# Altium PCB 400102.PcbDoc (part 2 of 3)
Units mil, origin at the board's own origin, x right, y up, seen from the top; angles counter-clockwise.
Board outline 3703.69 x 2381.89 mil, 2 copper layers (Top Layer, Bottom Layer), stack 61.8 mil thick; 220 components, 149 nets, 880 pads, 750 vias.
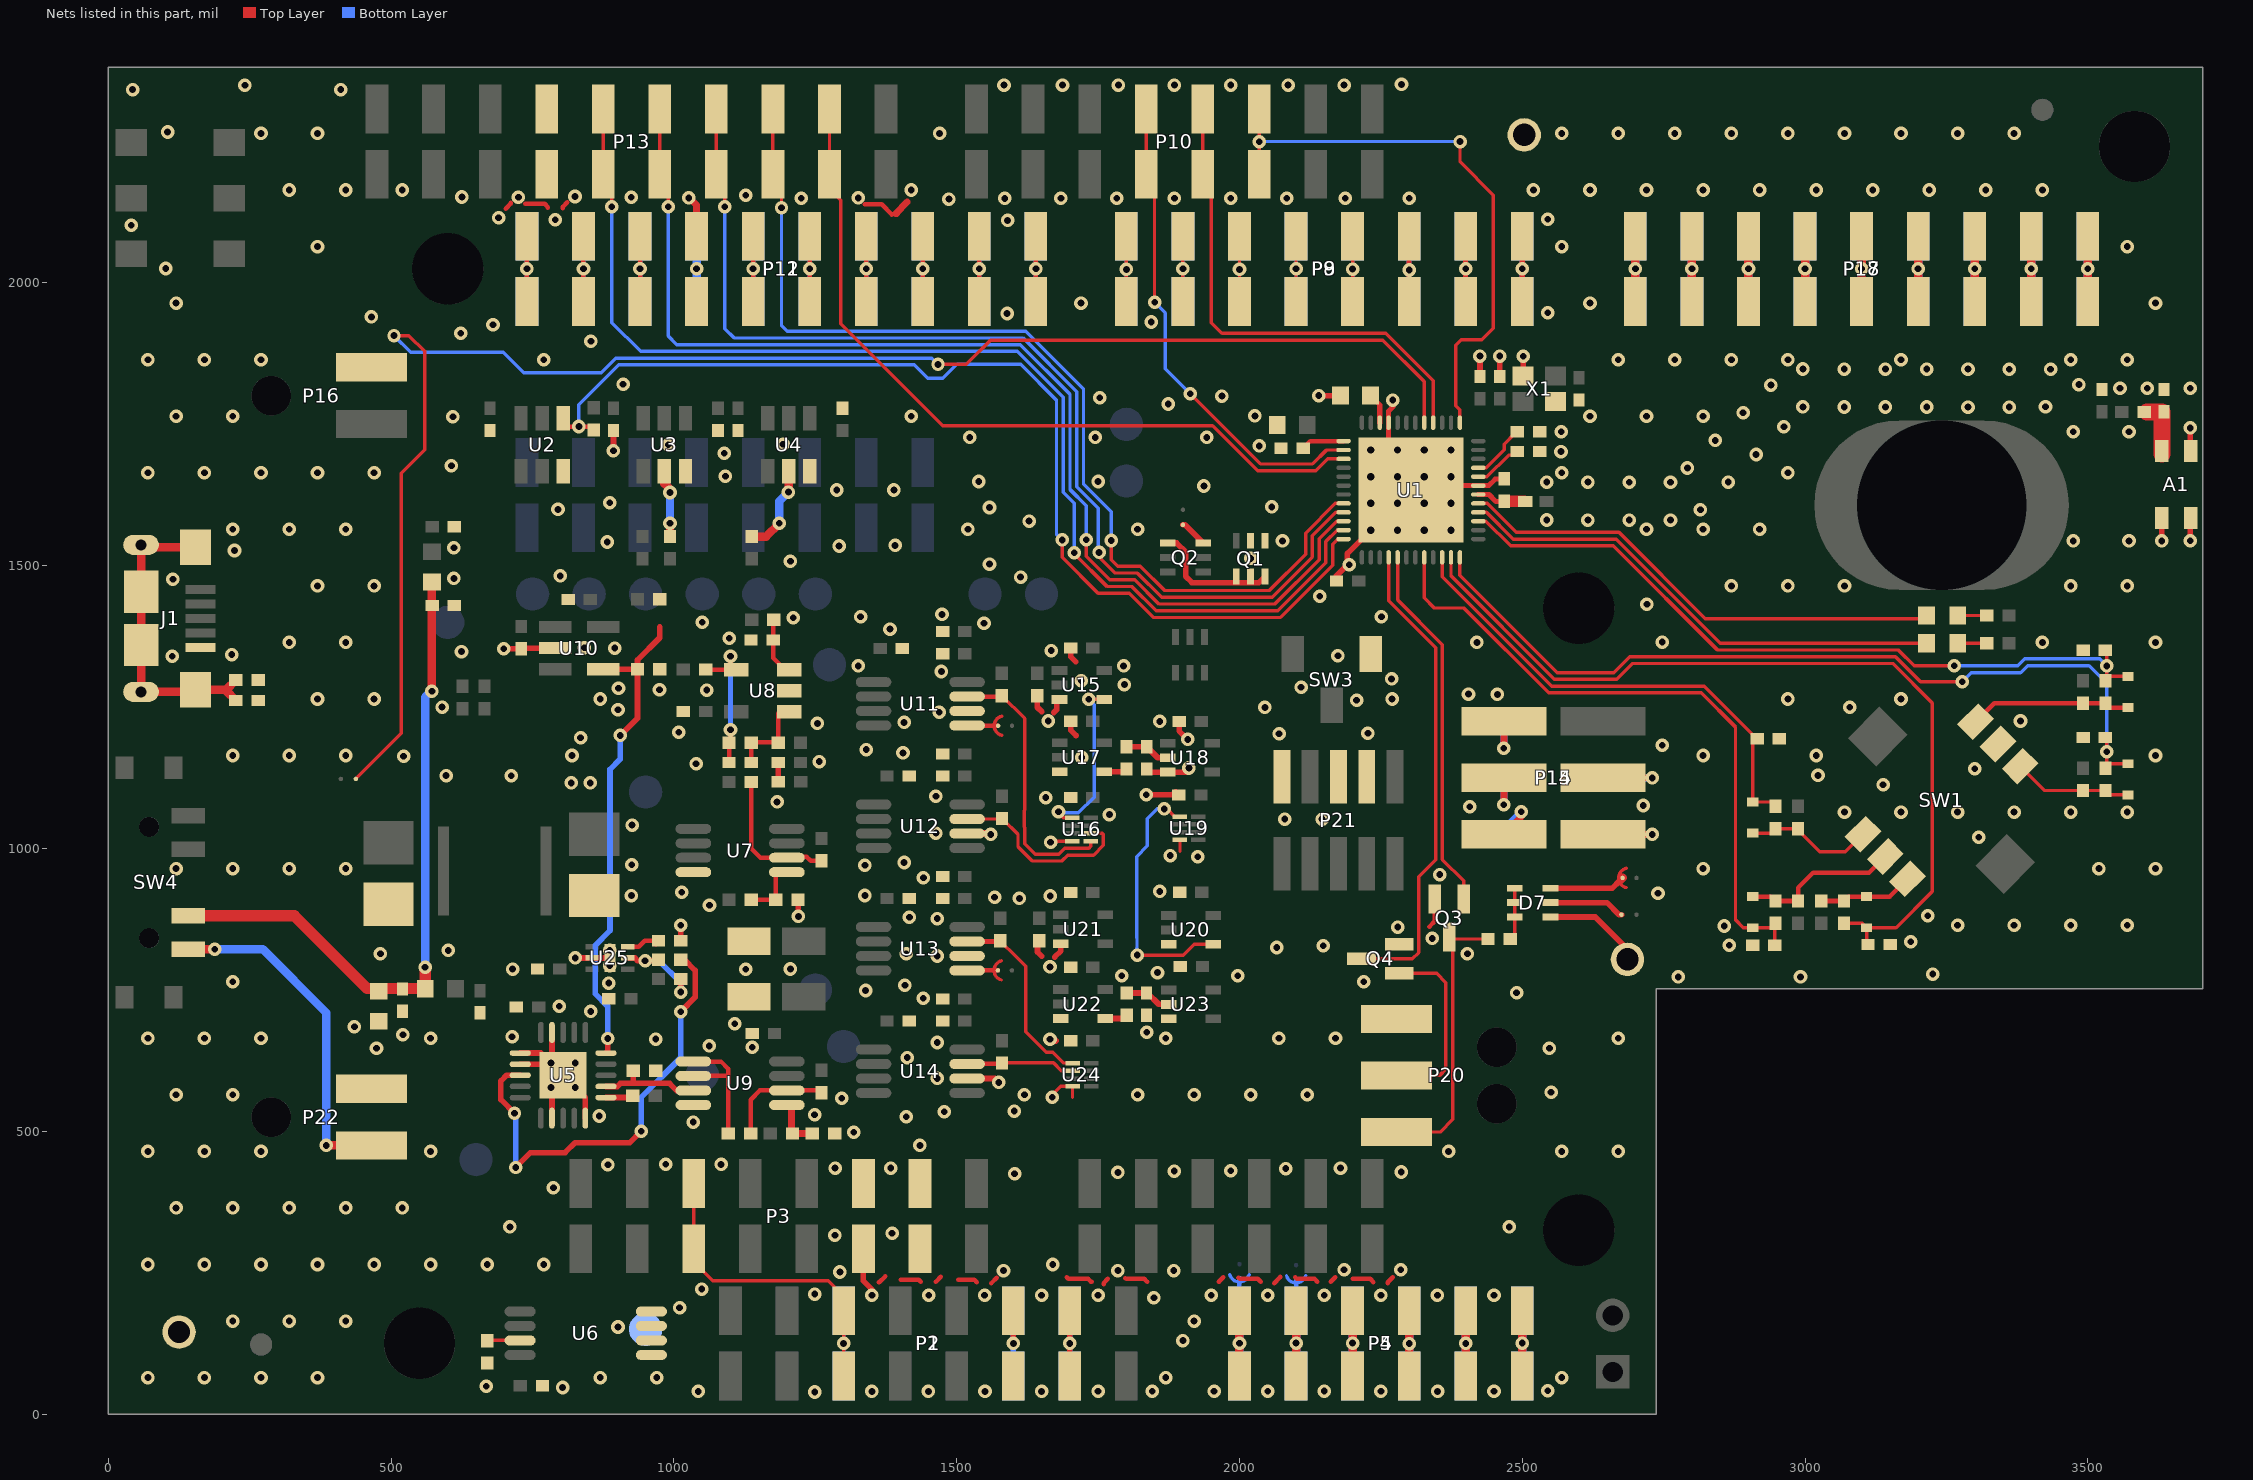
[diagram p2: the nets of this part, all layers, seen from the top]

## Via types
v1: diameter 24, hole 12, Top Layer to Bottom Layer, tented both sides, 666 vias
v2: diameter 23.62, hole 11.81, Top Layer to Bottom Layer, tented both sides, 68 vias
v3: diameter 25.98, hole 12.99, Top Layer to Bottom Layer, tented both sides, 16 vias

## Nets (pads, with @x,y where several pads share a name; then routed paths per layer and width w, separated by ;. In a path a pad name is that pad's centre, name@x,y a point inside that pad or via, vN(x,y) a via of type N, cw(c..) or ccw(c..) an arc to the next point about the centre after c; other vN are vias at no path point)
D2: P10.3 U1.37 | length 1044.3
  Top Layer w6: P10.3@2035,2192.17 v1(2035,2249.84) P10.3@2035,2307.52 ; U1.37@2389.76,1752.95 2389.76,1775.65 2382.22,1783.2 2382.22,1889.76 2391.89,1899.43 2428.43,1899.43 2449,1920 2449,2155 2390,2214 v1(2390,2250)
  Bottom Layer w6: v1(2035,2249.84) 2035.39,2250.23 2389.77,2250.23 v1(2390,2250)
D3: P10.4 U1.40 | length 892.9
  Top Layer w6: P10.4@1935,2307.52 P10.4@1935,2192.17 1935,2165.53 1950,2150.53 1950,1930 1969,1911 2258.41,1911 2342.52,1826.89 U1.40@2342.52,1752.95
D4: P10.5 U1.2 | length 868.3
  Top Layer w6: P10.5@1835,2307.52 P10.5@1835,2192.17 1849.69,2177.48 v2@1849.69,1966 ; v2(1913.11,1804) 2037.11,1680 2129.15,1680 2153.87,1704.72 U1.2@2184.06,1704.72
  Bottom Layer w6: v2(1850,1966) 1869,1947 1869,1848.11 v2(1913.11,1804)
D9: P13.2 U1.3 | length 1393.2
  Top Layer w6: P13.2@1275,2307.52 P13.2@1275,2192.17 1275,2166 1295,2146 1295,1927.91 1475,1747.91 1952.37,1747.91 2032.18,1668.09 2135.04,1668.09 2155.92,1688.98 U1.3@2184.06,1688.98
D10: P13.3 U1.8 | length 1789.3
  Top Layer w6: P13.3@1175,2192.17 P13.3@1175,2307.52 ; v2(1190.13,2133) P13.3@1190.13,2177.04 ; v1(1773.15,1544.64) 1773.15,1510.85 1784.94,1499.05 1824.63,1499.05 1867.47,1456.21 2052.86,1456.21 2117,1520.35 2117,1557.72 2169.52,1610.24 U1.8@2184.06,1610.24
  Bottom Layer w6: v2(1190.13,2133) 1190.13,1925 1200.41,1914.72 1622.12,1914.72 1724.09,1812.74 1724.09,1644.74 1773.15,1595.69 v1(1773.15,1544.64)
D11: P13.4 U1.9 | length 1917.6
  Top Layer w6: P13.4@1075,2307.52 P13.4@1075,2192.17 1090,2177.16 v1(1090,2135) ; v1(1751.82,1523.61) 1751.82,1515.34 1780.01,1487.15 1819.7,1487.15 1862.54,1444.31 2057.8,1444.31 2128.91,1515.42 2128.91,1552.79 2170.6,1594.49 U1.9@2184.06,1594.49
  Bottom Layer w6: v1(1090,2135) 1090,1919 1106.19,1902.81 1617.19,1902.81 1712.19,1807.81 1712.19,1639.81 1750.05,1601.95 1750.05,1525.39 v1(1751.82,1523.61)
D12: P13.5 U1.10 | length 2031.2
  Top Layer w6: P13.5@975,2307.52 P13.5@975,2192.17 989.76,2177.4 v1(989.76,2135) ; v1(1729.14,1546) 1729.14,1516.73 1770.62,1475.24 1814.77,1475.24 1857.61,1432.4 2062.73,1432.4 2140.81,1510.48 2140.81,1547.86 2171.69,1578.74 U1.10@2184.06,1578.74
  Bottom Layer w6: v1(989.76,2135) 989.76,1906.24 1005.09,1890.91 1612.26,1890.91 1700.28,1802.88 1700.28,1634.88 1729.14,1606.02 v1(1729.14,1546)
D13: P13.6 U1.11 | length 2120.6
  Top Layer w6: P13.6@875,2307.52 P13.6@875,2192.17 890,2177.16 v1(890,2135) ; v1(1707.81,1522.97) 1707.81,1521.22 1765.69,1463.34 1809.84,1463.34 1852.68,1420.5 2067.66,1420.5 2152.72,1505.55 2152.72,1542.93 2172.78,1562.99 U1.11@2184.06,1562.99
  Bottom Layer w6: v1(890,2135) 890,1930 941,1879 1607.33,1879 1688.38,1797.95 1688.38,1629.95 1707.48,1610.85 1707.48,1523.63 v1@1706.81,1522.97
DEC1: C4.1 U1.1 | length 76
  Top Layer w8: C4.1@2112.99,1708.62 2124.84,1720.47 U1.1@2184.06,1720.47
DEC2: C6.2 U1.32 | length 79
  Top Layer w6: U1.32@2422.24,1657.48 2437.44,1657.48 2475.75,1695.78 C6.2@2485.39,1695.78
DEC3: C7.1 U1.33 | length 96
  Top Layer w6: U1.33@2422.24,1673.23 2436.22,1673.23 2468.15,1705.16 2468.15,1715.05 C7.1@2487.21,1734.11
DEC4: C10.2 U1.46 | length 54.7
  Top Layer w9: C10.2@2231.72,1800.86 2248.03,1784.55 U1.46@2248.03,1752.95
EXT_TRIG_IN: P20.2 Q4.1 | length 334.2
  Top Layer w6: P20.2@2277.83,598.66 2353.66,598.66 2365,610 2365,763 2348.59,779.41 Q4.1@2282.46,779.41
EXT_TRIG_OUT: P20.1 Q3.3 R50.1 | length 498.1
  Top Layer w6: P20.1@2277.83,498.66 2354.66,498.66 2376.91,520.91 2376.91,837.63 Q3.3@2374.54,840 ; Q3.3@2371,843.54 Q3.3@2374.54,840 ; R50.1@2439.32,840 Q3.3@2374.54,840
GND: A1.2 C1.2 C2.2 C3.1 C4.2 C5.2 C6.1 C7.2 C8.2 C9.2 C10.1 C11.2 C12.2 C13.2 C14.1 C15.1 C16.1 C17.2 C18.2 C19.2 C20.2 C21.2 C22.2 C23.1 C24.1 C25.1 C26.1 C28.1 C29.1 C30.1 C31.1 C32.2 C33.1 C34.1 C35.1 C36.2 C37.1 C38.2 C39.2 C40.1 C41.2 C42.1 C43.1 C44.1 C45.2 C46.1 C47.1 C48.1 C49.1 C50.1 C51.1 C52.1 C53.1 C54.1 C55.1 C56.1 C57.1 C58.2 C59.2 C60.2 C61.2 C62.2 C63.1 C64.1 C65.1 C66.1 C67.1 J1.5 P1.6 P1.7 P2.6 P2.7 P3.6 P3.7 P11.7 P12.7 P13.7 P16.1 P20.3 P21.3 P21.5 P21.9 P22.1 Q1.4 Q1.5 Q3.2 Q4.2 R5.1 R6.2 R11.1 R29.1 R30.1 R32.1 R36.1 R37.1 R41.1 R45.1 R49.2 SW1.5 SW3.3 TP9.1 TP10.1 TP11.1 U1.31 U1.45 U1.49 U2.3 U3.3 U4.3 U5.2 U5.5 U5.14 U5.16 U5.17 U5.21 U6.1 U6.2 U6.3 U6.4 U7.4 U8.2 U9.4 U10.2 U11.6 U12.6 U13.6 U14.6 U15.3 U16.4 U17.3 U18.3 U19.4 U20.3 U21.3 U22.3 U23.3 U24.4 U25.2 U25.7 X1.2 X1.4 | length 3256.3
  Top Layer w6: v1@1671.67,1010.33 1674.43,1013.09 U16.4@1704.66,1013.09 ; 1675,570.69 1683.64,579.33 U24.4@1704.81,579.33 1704.81,559.67 ; 1894.76,995.34 U19.4@1894.76,1015.16 ; v1@1919.36,990.56 1924.38,985.54 v1(1926.16,985.54)
  Top Layer w8: 702.29,2131.49 711.3,2140.5 711.3,2141.74 ; 736.82,2139.88 771.44,2139.88 777.18,2134.14 777.18,2133.13 ; 803.15,2132.22 803.15,2134.47 811.62,2142.95 ; 1337.36,2139.06 1367.43,2139.06 1385.42,2121.07 ; 1361.86,232.82 1363.05,232.82 1374.02,243.79 ; 1401.07,237.9 1432.56,237.9 1436.55,233.92 ; 1463.28,233.92 1471.9,242.54 ; 1502.92,237.26 1531.4,237.26 1535.43,233.23 ; 1561.44,231.62 1571.08,241.26 ; 1694.63,241.78 1697.35,239.06 1732.26,239.06 1737.4,233.92 1738.4,233.92 ; 1759.84,229.41 1759.84,231.62 1767.28,239.06 ; 1798.27,240.35 1799.56,239.06 1831.35,239.06 1836.49,233.92 ; 1964.04,233.92 1963.38,233.92 1971.34,241.88 ; 1998.27,240.93 2000.14,239.06 2032.45,239.06 2037.59,233.92 ; 2061.59,231.49 2071.72,241.63 2071.72,242.6 ; 2098.27,241.63 2100.92,238.98 2132.62,238.98 2137.68,233.92 ; 2161.42,233.92 2169.29,241.79 ; 2200.14,239.06 2231.02,239.06 2236.85,233.23 ; 2262.32,231.62 2262.32,233.23 2270.97,241.88 ; 2336,862 2345.41,871.41 Q3.2@2345.41,910.46
  Top Layer w9: C36.2@1415.97,1127.93 C36.2@1416.95,1126.94 ; U1.49@2263.78,1720.47 U1.45@2263.78,1752.95 2263.78,1773.49 2271.15,1780.86 v1(2271.15,1792.86) ; U1.49@2327.46,1641.86 2440.91,1641.86 2452.21,1653.16 C3.1@2468.46,1653.16
  Top Layer w10: v1(699,1353.34) 728.12,1353.34 730.07,1355.29 C28.1@731,1354.37 ; U5.17@728.21,618.69 U5.21@784.31,618.69 ; U5.16@728.21,638.37 764.63,638.37 v1(782.35,620.65) U5.21@784.31,618.69 ; C28.1@729.95,1353.32 C28.1@731,1354.37 ; U5.2@784.31,523.21 U5.21@784.31,579.32 ; U5.14@784.31,674.79 U5.21@784.31,618.69 ; U10.2@790.17,1354.37 C28.1@731,1354.37 ; v1(825.42,806.52) U25.2@855.13,806.52 ; U5.5@843.37,523.21 843.37,559.63 v1(825.65,577.35) U5.21@804,599 U5.21@784.31,618.69 ; U25.2@855.13,806.52 U25.7@886.62,806.52 v2(886.62,820.3) ; v1(893,1703.41) 893,1728.98 898,1733.98 C12.2@893,1738.98 ; C57.1@1012.13,836.95 v1(1012.13,864.45) ; C26.1@1184.32,1152.3 1184.32,1118.35 C23.1@1184.56,1118.1 ; R29.1@1219.24,909.26 1223.58,904.92 1220,901.34 v1(1220,880) ; P3.6@1335,293.01 P3.6@1335,292.17 1335,235.56 1350,220.56 v1(1350,210) ; U14.6@1518.33,593.48 1567.04,593.48 v1(1574.14,586.38) ; P2.6@1600,182.68 1600,124.68 v1(1600.31,125) ; R41.1@1642.41,1270.42 1642.41,1249.88 1650.5,1241.79 ; R45.1@1642.97,837.16 1642.97,816.9 1650.5,809.37 ; 1671.56,1240.43 1676.6,1245.47 1676.6,1263.13 1677.29,1263.82 U15.3@1681.78,1263.82 ; 1673.09,808 1684.18,819.1 U21.3@1684.18,831.7 ; P2.7@1700,67.32 v1(1700,125) P2.7@1700,182.68 ; C48.1@1701.47,1225 1701.47,1209.34 1711.02,1199.79 ; C53.1@1701.46,1354.37 1701.46,1339.27 1710.32,1330.42 ; v1(1835,1095) 1882.06,1095 1887.06,1100 C50.1@1892.68,1094.38 ; C34.1@1835.91,1140.69 1841.62,1134.97 U18.3@1873.41,1134.97 v1@1910.49,1134.97 ; C49.1@1893.22,1224.74 1893.22,1208 v1@1904,1197.22 ; C9.2@2066.57,1748.86 C9.2@2072.48,1754.76 ; C4.2@2069.49,1711.83 C4.2@2073.46,1707.86 ; v1(2140,1800.86) C10.1@2178.57,1800.86 ; U1.49@2316,1577 2246.29,1577 v3(2232.28,1562.99) 2190.84,1521.55 2190.84,1501.83 2173.84,1484.83 ; C8.2@2425.15,1834.54 v1(2425.15,1870.81) ; C2.2@2460.15,1834.54 v1(2460.15,1870.81) ; X1.2@2501.61,1835.5 v1(2501.66,1870.52) v1(2501.66,1870.52) ; C1.2@2600.15,1792.56 2598.84,1793.87 C1.2@2600.15,1795.17 ; v1(3630.83,1543.92) A1.2@3630.83,1584.65 ; v1(3681.1,1544.22) A1.2@3681.1,1583.74 ; A1.2@3681.1,1703.66 v1(3681.1,1743.79) ; A1.2@3682.01,1580.01 A1.2@3682.01,1584.65 ; A1.2@3682.01,1702.76 A1.2@3682.01,1704.09 ; 2173.84,1484.83 2171.46,1482.46 C5.2@2171.46,1472.86 2173.84,1475.24 2173.84,1484.83
  Top Layer w12: v1@1032,2146 1040,2138 P12.7@1040,2082.68 ; 1394.03,2123.06 1392.37,2123.06 1412.38,2143.07 ; U12.6@1518.33,1026.55 1564.1,1026.55 1562.55,1025 v1(1560,1025) ; v1(1665,662.88) 1671.71,662.88 v1@1674.59,660
  Top Layer w15: U3.3@1020.4,1658.62 U3.3@1020.4,1666.73
  Bottom Layer w10: P1.6@1600,67.32 1600,125 v1(1600.31,125) ; v1@1600,125.31 P1.6@1600,182.68 ; P1.7@1700,67.32 v1(1700,125) P1.7@1700,182.68 ; v1(1835,1095) v1@1835.71,1094.29
  Bottom Layer w15: P11.7@1040,1967.32 P11.7@1040,2082.68
  other v1: 1249.1,39 1042.95,40 1350,40 1450,40 1550,40 1650,40 1750,40.35 1845.57,40.35 1955,40.35 2050,40.35 2150,40.7 2250,40.35 2350.23,40 2450,40.35 2545,41.04 803,47 668,49 69.75,64.45 169.75,64.45 269.75,64.45 369.75,64.45 869.75,64.45 969.75,64.45 1869.75,64.45 2569.75,64.45 1900,129.92 901,154 219.75,164.45 319.75,164.45 419.75,164.45 1919.75,164.45 1010,188 1848.66,205.49 1450.43,210 1549.37,210 1650,210 1750,210 1950,210 2050,210 2150,210 2250,210 2350,210 2450,210 1249.1,212.23 1049,221 1293.44,251.16 1582.67,253.69 1785,253.69 1883.79,253.69 2185,255 2285,255 69.75,264.45 169.75,264.45 269.75,264.45 369.75,264.45 469.75,264.45 569.75,264.45 669.75,264.45 769.75,264.45 1669.75,264.45 1284.55,316 1385.72,319.62 710,331 2477,331 119.75,364.45 219.75,364.45 319.75,364.45 419.75,364.45 519.75,364.45 786.88,400 1602.31,425 1785,427.32 2286,428 1884.52,429.63 1984.53,430.18 2081.69,434 1284.94,435 1383.47,435 2178.57,435 883.27,440.94 985.32,441.69 1083.35,441.52 69.75,464.45 169.75,464.45 269.75,464.45 569.75,464.45 2369.75,464.45 2569.75,464.45 2669.75,464.45 1435,475 1318,498.36 1034.05,516.26 1410.77,525.59 868,527 1248.7,529.15 1478,534.62 1601.83,535.71 1296.65,558.44 1668.98,560.04 119.75,564.45 219.75,564.45 1619.75,564.45 1819.75,564.45 1919.75,564.45 2019.75,564.45 2119.75,564.45 2551,569 782.35,577.35 1465.53,593.48 825.65,620.65 1412.38,630.24 474,647 2548,647 1138.31,648.66 1062.32,650.97 1465.53,657.04 968,663 69.75,664.45 169.75,664.45 269.75,664.45 569.75,664.45 1869.75,664.45 2069.75,664.45 2169.75,664.45 2669.75,664.45 713.83,667 520.78,670.69 1835.91,675 435,685 1107.68,690 853,712 797,721 1440.84,735.21 2490,745 1338.8,749 1408.44,758.11 884.76,762.12 219.75,764.45 2219.75,764.45 2776,773 2992,773 1792,775 1997,775.05 3226,778 1855,780.67 714.73,786.83 1126.78,786.49 1206,787 1665,790.65 1465.53,810.01 481,813.81 1410.77,813.82 2403,814 601,819.87 2066,825 2148,828 2866,829 3187,835 2341,841 2280,861 2857,863 3269.75,864.45 3369.75,864.45 3469.75,864.45 3569.75,864.45 1465.53,876.13 1416.31,878.64 3217,881 1062.84,899.74 1610.78,911.79 1567,914 924.76,916.87 1337.57,916.94 1665.2,916 2740,921 1013.91,922.62 1859,924.08 1441.04,948.38 2354,954 119.75,964.45 219.75,964.45 319.75,964.45 419.75,964.45 2819.75,964.45 3519.75,964.45 3619.75,964.45 1337.57,970.45 925.46,971.23 1407.02,975.25 1877.56,987.48 1666,1011 3307.09,1020.1 1463.28,1027.24 926,1041.53 2080,1052 2146,1052 1770,1060 3069.75,1064.45 3169.75,1064.45 3269.75,1064.45 3369.75,1064.45 3469.75,1064.45 3569.75,1064.45 2407,1074 2713.82,1076.13 1182.28,1082.36 1657.48,1090 1463.28,1092.49 3138,1112.69 818.5,1116 851.89,1116 712.29,1128.75 597,1129 3023,1129.35 3300,1141.25 1910.49,1142.33 1039.12,1149.93 1257.08,1153.69 1721,1161 522,1163 219.75,1164.45 319.75,1164.45 419.75,1164.45 819.75,1164.45 2819.75,1164.45 3019.75,1164.45 3619.75,1164.45 1405,1169 1340,1175 2747.71,1182.56 1908.34,1192.89 835,1196 2070,1203 2227,1204 1008.62,1205.62 1253.59,1221.27 1407,1223 1859,1224.72 1662,1225.44 3381,1225.54 1469,1241 901.02,1245.3 2044.89,1249.46 3079.09,1249.63 590,1250 2207,1262 369.75,1264.45 469.75,1264.45 869.75,1264.45 2269.75,1264.45 2969.75,1264.45 3169.75,1264.45 2456.04,1272.45 2405,1273 974.41,1280.65 1057.92,1280.18 902,1283.24 2109,1285 1796.51,1289.86 1720.19,1296.73 2269,1300 1473,1313 1326,1323 1795,1323 113,1340 2174,1341 218,1343 624.36,1348.32 1667.32,1350 895.48,1354.37 841.59,1355 319.75,1364.45 419.75,1364.45 2419.75,1364.45 3419.75,1364.45 3619.75,1364.45 2747.71,1365 1097.64,1372 1382,1388 1548.2,1398.47 1050,1400 1210.79,1408 1330,1410 2251,1410 1474,1414 2720.43,1431.78 2142,1446 369.75,1464.45 469.75,1464.45 2869.75,1464.45 2969.75,1464.45 3069.75,1464.45 3469.75,1464.45 3569.75,1464.45 114,1476 611,1477.58 1613,1480 799,1482 1558,1503 1206,1508 2020,1513 223,1527 611,1532 1292,1535 1391,1536 882,1542 3474.41,1543.92 3572.83,1543.92 2076,1544 219.75,1564.45 319.75,1564.45 419.75,1564.45 1519.75,1564.45 1819.75,1564.45 2719.75,1564.45 2819.75,1564.45 2919.75,1564.45 1628,1579 2543.15,1580.86 2616.15,1580.81 2689.15,1580.76 2762.15,1580.72 795,1599.55 2814.96,1598.98 1558,1603 2057,1604 886.62,1611.5 1287.7,1634 1389,1634 1937,1641 2543.15,1647.86 2616.15,1647.86 2689.15,1647.81 2762.15,1647.76 2864.17,1647.86 1539,1649 1750,1649 1091,1658.45 69.75,1664.45 169.75,1664.45 269.75,1664.45 369.75,1664.45 469.75,1664.45 2569.75,1664.45 2969.75,1664.45 2792.13,1672.84 606.49,1677 2913.39,1696.74 1088.77,1699 2568.5,1701.86 2034.84,1711.83 990,1713.98 1193,1715 2841.34,1721.72 1523,1727 1745,1727 1942,1727 2568.9,1736.86 3474.41,1736.86 3572.83,1736.86 2962.6,1745.62 609.14,1763.59 119.75,1764.45 219.75,1764.45 1419.75,1764.45 2619.75,1764.45 2719.75,1764.45 2819.75,1764.45 2027.21,1765.02 2890.55,1770.61 2996.23,1780.81 3069.23,1780.76 3142.23,1780.72 3215.23,1780.67 3288.23,1780.62 3361.23,1780.57 3425.2,1781.17 1874,1786 1753,1797 1969,1800 3556.93,1813.98 3605,1813.98 3681.1,1813.98 2939.76,1819.49 3484.25,1820.38 910,1821 2996.23,1847.86 3069.23,1847.81 3142.23,1847.76 3215.23,1847.72 3288.23,1847.67 3361.23,1847.62 3434.23,1847.57 69.75,1864.45 169.75,1864.45 269.75,1864.45 769.75,1864.45 2669.75,1864.45 2769.75,1864.45 2869.75,1864.45 2969.75,1864.45 3169.75,1864.45 3469.75,1864.45 3569.75,1864.45 853.16,1897 623,1911 680,1926 1844,1931 465,1940 1589,1946 2545,1947.56 119.75,1964.45 1719.75,1964.45 2619.75,1964.45 3619.75,1964.45 101.21,2025.59 1040,2025 369.75,2064.45 2569.75,2064.45 3569.75,2064.45 40.39,2102 1590,2110.7 790,2111.94 2545.03,2112.64 690,2115.35 1486.24,2148.42 1584.9,2149.51 1026.17,2150.53 1225.03,2150.03 1325.89,2150.53 1684.18,2150.03 1782.91,2150.03 1885,2150.03 1984.53,2150.03 2083.67,2150.03 2186.98,2150.03 2300,2150.03 725,2151.44 924.41,2151.44 625,2152.02 825,2153 1127.08,2155 319.75,2164.45 419.75,2164.45 519.75,2164.45 1419.75,2164.45 2519.75,2164.45 2619.75,2164.45 2719.75,2164.45 2819.75,2164.45 2919.75,2164.45 3019.75,2164.45 3119.75,2164.45 3219.75,2164.45 3319.75,2164.45 3419.75,2164.45 269.75,2264.45 369.75,2264.45 1469.75,2264.45 2569.75,2264.45 2669.75,2264.45 2769.75,2264.45 2869.75,2264.45 2969.75,2264.45 3069.75,2264.45 3169.75,2264.45 3269.75,2264.45 3369.75,2264.45 104.69,2266.94 42.68,2342 410.72,2342 241.38,2349.49 1583.54,2350 1687,2350 1786,2350 1885,2350 1984.53,2350 2086.01,2350 2185,2350 2286.43,2351.16
  other v2: 886.62,792.74 2193.84,1501.83
  other v3: 2279.53,1562.99 2326.77,1562.99 2374.02,1562.99 2232.28,1610.24 2279.53,1610.24 2326.77,1610.24 2374.02,1610.24 2232.28,1657.48 2279.53,1657.48 2326.77,1657.48 2374.02,1657.48 2232.28,1704.72 2279.53,1704.72 2326.77,1704.72 2374.02,1704.72
JOYSTICK_BUTTON_FILTERED: C22.1 D6.3 R22.2 U1.20 | length 1174.9
  Top Layer w6: U1.20@2326.77,1514.76 2326.77,1443.23 2344.72,1425.28 2396.88,1425.28 2546.88,1275.28 2816.72,1275.28 2877.09,1214.91 2877.09,873.91 2891.04,859.96 D6.3@2907.64,859.96 2939.76,859.96 R22.2@2946.68,866.88 ; C22.1@2946.68,829 R22.2@2946.68,866.88 ; R22.2@2947.64,867.83 R22.2@2946.68,866.88
JOYSTICK_BUTTON_UNFILTERED: D6.1 R17.1 R22.1 SW1.2 | length 283.9
  Top Layer w8: D6.1@2907.64,915.08 2939.76,915.08 R22.1@2947.64,907.2 R17.1@2987.64,907.2 2987.64,930.55 3014.19,957.11 3113.15,957.11 SW1.2@3141.96,985.91
JOYSTICK_DOWN_FILTERED: C19.1 D3.3 R19.2 U1.23 | length 1550.7
  Top Layer w6: U1.23@2374.02,1514.76 2374.02,1481.98 2556.91,1299.09 2666.93,1299.09 2695.07,1327.23 3155.09,1327.23 3225,1257.33 3225,924 3160.96,859.96 D3.3@3108.82,859.96 3108.82,830.5 C19.1@3111.32,828 ; R19.2@3068.82,867.83 3100.94,867.83 3104.68,864.09 D3.3@3104.68,859.96
JOYSTICK_DOWN_UNFILTERED: D3.1 R14.1 R19.1 SW1.3 | length 157.7
  Top Layer w8: R14.1@3028.82,907.2 R19.1@3068.82,907.2 ; R19.1@3076.69,915.08 D3.1@3108.82,915.08 3149.91,915.08 SW1.3@3181.35,946.52
JOYSTICK_LEFT_FILTERED: C20.1 D4.3 R20.2 U1.22 | length 867.3
  Top Layer w6: U1.22@2358.27,1514.76 2358.27,1480.73 2551.81,1287.19 2821.65,1287.19 2914.84,1194 2907.64,1186.8 D4.3@2907.64,1082.36 2939.76,1082.36 R20.2@2947.64,1074.49
JOYSTICK_LEFT_UNFILTERED: D4.1 R15.1 R20.1 SW1.1 | length 227
  Top Layer w6: D4.1@2907.64,1027.24 2939.76,1027.24 R20.1@2947.64,1035.12 R15.1@2987.64,1035.12 ; R15.1@2987.64,1032.46 3026,994.09 3071.36,994.09 SW1.1@3102.57,1025.31
JOYSTICK_RIGHT_FILTERED: C21.1 D5.3 R21.2 U1.24 | length 1507.4
  Top Layer w6: U1.24@2389.76,1514.76 2389.76,1483.46 2562.23,1311 2662,1311 2690.14,1339.14 3160.02,1339.14 3204.16,1295 v2(3278,1295) ; C21.1@3531.1,1196.35 3533.46,1193.99 v1(3533.46,1171.26) R21.2@3533.46,1144.11 ; R21.2@3539.29,1149.93 D5.3@3571.42,1149.93
  Bottom Layer w6: v2(3278,1295) 3294.09,1311.09 3381.08,1311.09 3393.45,1323.46 3502.2,1323.46 3533.46,1292.19 v1(3533.46,1171.26)
JOYSTICK_RIGHT_UNFILTERED: D5.1 R16.1 R21.1 SW1.6 | length 200.9
  Top Layer w6: SW1.6@3380.4,1145.57 3423.28,1102.69 R16.1@3491.42,1102.69 R21.1@3531.42,1102.69 ; R21.1@3539.29,1094.82 D5.1@3571.42,1094.82
JOYSTICK_UP_FILTERED: C18.1 D2.3 R18.2 U1.27 | length 1320.4
  Top Layer w6: U1.27@2422.24,1578.74 2435.66,1578.74 2479.31,1535.09 2661.23,1535.09 2845.28,1351.05 3164.95,1351.05 3193,1323 v2(3264,1323) ; C18.1@3531.1,1350.72 3537.85,1350.72 3533.46,1346.33 v1(3533.46,1322.92) R18.2@3533.46,1298.47 ; R18.2@3539.29,1304.3 D2.3@3571.42,1304.3
  Bottom Layer w6: v2(3264,1323) 3376.15,1323 3388.51,1335.36 3521.02,1335.36 v1(3533.46,1322.92)
JOYSTICK_UP_UNFILTERED: D2.1 R13.1 R18.1 SW1.4 | length 275.5
  Top Layer w8: SW1.4@3301.62,1224.35 3334.32,1257.05 R13.1@3491.42,1257.05 R18.1@3531.42,1257.05 ; R18.1@3539.29,1249.18 D2.1@3571.42,1249.18
LED1: LED1.1 U1.29 | length 871.7
  Top Layer w6: U1.29@2422.24,1610.24 2437.84,1610.24 2489.17,1558.91 2671.09,1558.91 2823.39,1406.61 LED1.1@3209.56,1406.61
LED2: LED2.1 U1.28 | length 888.7
  Top Layer w6: U1.28@2422.24,1594.49 2436.75,1594.49 2484.24,1547 2666.16,1547 2850.21,1362.95 LED2.1@3215.08,1362.95
NetA1_1: A1.1 C15.2 R7.2 | length 99.8
  Top Layer w30: R7.2@3605,1771.98 3630.83,1771.98 A1.1@3630.83,1698
NetC3_2: C3.2 L1.1 U1.30 | length 86.6
  Top Layer w9: U1.30@2422.24,1625.98 2441.05,1625.98 2453.25,1613.79 C3.2@2468.46,1613.79
  Top Layer w20: C3.2@2468.15,1613.98 L1.1@2503.46,1613.98
NetC25_2: C25.2 R25.2 U8.3 | length 103.8
  Top Layer w8: R25.2@1175.69,1403.64 C25.2@1175.69,1369 1175.69,1336.88 1196.17,1316.4 U8.3@1204.24,1316.4
NetC27_1: C27.1 R24.1 R26.2 U8.1 | length 162.9
  Top Layer w8: R26.2@1136.69,1186.89 1137.91,1188.12 R24.1@1179.13,1188.12 ; C27.1@1136.76,1152.36 R26.2@1136.76,1186.81 ; R24.1@1183.8,1192.78 R24.1@1179.13,1188.12 ; U8.1@1204.24,1241.6 1186.76,1241.6 1184.32,1239.16 R24.1@1184.32,1186.89 1183.09,1188.12 R24.1@1179.13,1188.12
NetC27_2: C27.2 R23.2 R26.1 U8.4 | length 259
  Top Layer w8: R23.2@1055.92,1314.4 1057.92,1316.4 1100,1316.4 v1(1100,1340) ; R26.1@1097.32,1186.89 1100,1189.58 1097.84,1191.73 1100,1193.89 v1(1100,1210) ; C27.2@1097.39,1152.36 R26.1@1097.32,1186.89
  Bottom Layer w8: v1(1100,1210) v1(1100,1340)
NetC34_2: C34.2 R40.2 U18.2 | length 81.5
  Top Layer w10: R40.2@1800,1180.06 C34.2@1835.91,1180.06 1855.4,1160.57 U18.2@1873.41,1160.57
NetC43_2: C43.2 R44.2 U23.2 | length 81.2
  Top Layer w10: R44.2@1800.44,744.59 C43.2@1835.88,744.59 ; C43.2@1837.11,744.59 1857.17,724.54 U23.2@1874.62,724.54
NetC57_2: C57.2 U25.6 | length 66
  Top Layer w8: U25.6@918.12,826.2 937.84,826.2 948.59,836.95 C57.2@972.76,836.95
  Top Layer w10: C57.2@967.91,832.09 C57.2@972.76,836.95
NetC60_1: C60.1 J1.6@57.69,1277.05 J1.6@57.69,1359.73 J1.6@57.69,1454.22 J1.6@57.69,1536.89 J1.6@154.14,1280.99 J1.6@154.14,1532.96 R49.1 | length 584.3
  Top Layer w15: J1.6@154.14,1532.96 61.62,1532.96 J1.6@57.69,1536.89 J1.6@57.69,1454.22 J1.6@57.69,1359.73 J1.6@57.69,1277.05 150.2,1277.05 J1.6@154.14,1280.99 208.3,1280.99 R49.1@225.31,1298 225.31,1297.75 208.29,1280.73 208.29,1279.02 C60.1@225.31,1262
NetC63_2: C63.2 C64.2 C66.2 FB1.1 FB2.1 SW4.3 | length 1192.3
  Top Layer w15: v1(572,1278) 572.07,1283.69 572.07,1471.35 FB1.1@572,1471.43
  Top Layer w20: SW4.3@145.9,880.94 329.06,880.94 457.54,752.46 560,752.46 v1(560,790)
  Bottom Layer w15: v1(560,790) 560,1267.68 570.32,1278 v1(572,1278)
NetD7_1: D7.1 D7.2 D7.3 R50.2 | length 93.4
  Top Layer w6: R50.2@2478.69,840 2487,848.31 D7.3@2487,878.82 D7.2@2487,904.41 D7.1@2487,930
NetD7_4: D7.4 TP5.1 | length 159.5
  Top Layer w10: D7.4@2549.99,878.82 2629.18,878.82 TP5.1@2686,822
NetD7_5: D7.5 SB7.2 | length 134.3
  Top Layer w10: D7.5@2549.99,904.41 2649.59,904.41 2671,883 SB7.2@2675.4,883
NetD7_6: D7.6 SB8.2 | length 134.9
  Top Layer w10: D7.6@2549.99,930 2659.4,930 2671.54,942.14 SB8.2@2675.4,946
  Top Layer w15: SB8.2@2675.4,946 SB8.2@2677.4,948
NetLED1_2: LED1.2 R10.1 | length 51.2
  Top Layer w6: LED1.2@3270.08,1412.13 R10.1@3321.32,1412.13
NetLED2_2: LED2.2 R12.1 | length 51.2
  Top Layer w6: LED2.2@3270.08,1362.95 R12.1@3321.32,1362.95
NetP1_3: P1.3 P2.3 P3.3 | length 685
  Top Layer w6: P3.3@1035,407.52 1035,269.23 1068.23,236 1272.52,236 1300,208.52 P2.3@1300,182.68 P2.3@1300,67.32
  Bottom Layer w6: P1.3@1300,67.32 v1(1300,125) P1.3@1300,182.68
NetP4_1: P4.1 P5.1 SB3.2 | length 287.8
  Top Layer w15: P5.1@2000,67.32 v1@2000,124.68 ; v1(2000,125.31) P5.1@2000,182.68
  Bottom Layer w8: P4.1@2000,182.68 2000,233.53 SB3.2@2000,240.4
  Bottom Layer w15: P4.1@2000,67.32 P4.1@2000,182.68
NetP4_2: P4.2 P5.2 SB4.2 | length 286.8
  Top Layer w15: P5.2@2100,67.32 v1(2100,125.52) P5.2@2100,182.68
  Bottom Layer w8: P4.2@2100,182.68 2100,231.89 SB4.2@2100,238.76
  Bottom Layer w15: P4.2@2100,67.32 v1(2100,125.52) P4.2@2100,182.68
NetP4_3: P4.3 P5.3 | length 230.7
  Top Layer w15: P5.3@2200,67.32 v1(2200,125.52) P5.3@2200,182.68
  Bottom Layer w15: P4.3@2200,67.32 P4.3@2200,182.68
NetP4_4: P4.4 P5.4 | length 230.7
  Top Layer w15: P5.4@2300,67.32 v1(2300,124.68) P5.4@2300,182.68
  Bottom Layer w15: P4.4@2300,67.32 P4.4@2300,182.68
NetP4_5: P4.5 P5.5 | length 230.7
  Top Layer w15: P5.5@2400,67.32 v1(2400,125) P5.5@2400,182.68
  Bottom Layer w15: P4.5@2400,67.32 P4.5@2400,182.68
NetP4_6: P4.6 P5.6 | length 230.7
  Top Layer w15: P5.6@2500,67.32 v1(2500,125.52) P5.6@2500,182.68
  Bottom Layer w15: P4.6@2500,67.32 v1(2500,125.52) P4.6@2500,182.68
NetP8_1: P8.1 P9.1 | length 230.7
  Top Layer w9: P9.1@2500,1967.32 v1(2500,2025) P9.1@2500,2082.68
  Bottom Layer w9: P8.1@2500,1967.32 v1(2500,2025) P8.1@2500,2082.68
NetP8_2: P8.2 P9.2 | length 230.7
  Top Layer w9: P9.2@2400,1967.32 v1(2400,2025) P9.2@2400,2082.68
  Bottom Layer w9: P8.2@2400,1967.32 v1(2400,2025) P8.2@2400,2082.68
NetP8_3: P8.3 P9.3 | length 230.7
  Top Layer w9: P9.3@2300,1967.32 v1(2300,2023) P9.3@2300,2082.68
  Bottom Layer w9: P8.3@2300,1967.32 v1(2300,2023) P8.3@2300,2082.68
NetP8_4: P8.4 P9.4 | length 230.7
  Top Layer w6: P9.4@2200,1967.32 P9.4@2200,2082.68
  Bottom Layer w6: P8.4@2200,1967.32 v1(2200,2024.5) P8.4@2200,2082.68
NetP8_5: P8.5 P9.5 | length 230.7
  Top Layer w6: P9.5@2100,1967.32 P9.5@2100,2082.68
  Bottom Layer w6: P8.5@2100,1967.32 v1(2100,2025) P8.5@2100,2082.68
NetP8_6: P8.6 P9.6 | length 230.7
  Top Layer w6: P9.6@2000,1967.32 v1(2000,2024) P9.6@2000,2082.68
  Bottom Layer w6: P8.6@2000,1967.32 v1(2000,2024) P8.6@2000,2082.68
NetP8_7: P8.7 P9.7 | length 230.7
  Top Layer w6: P9.7@1900,1967.32 v1(1900,2025) P9.7@1900,2082.68
  Bottom Layer w6: P8.7@1900,1967.32 v1(1900,2025) P8.7@1900,2082.68
NetP8_8: P8.8 P9.8 | length 230.7
  Top Layer w6: P9.8@1800,1967.32 v1(1800,2024) P9.8@1800,2082.68
  Bottom Layer w6: P8.8@1800,1967.32 v1(1800,2024) P8.8@1800,2082.68
NetP11_1: P11.1 P12.1 | length 230.7
  Top Layer w8: P12.1@1640,1967.32 v1(1640,2025) P12.1@1640,2082.68
  Bottom Layer w8: P11.1@1640,1967.32 v1(1640,2025) P11.1@1640,2082.68
NetP11_2: P11.2 P12.2 | length 230.7
  Top Layer w8: P12.2@1540,1967.32 v1(1540,2025) P12.2@1540,2082.68
  Bottom Layer w8: P11.2@1540,1967.32 v1(1540,2025) P11.2@1540,2082.68
NetP11_3: P11.3 P12.3 | length 230.7
  Top Layer w8: P12.3@1440,1967.32 v1(1440,2025) P12.3@1440,2082.68
  Bottom Layer w8: P11.3@1440,1967.32 v1(1440,2025) P11.3@1440,2082.68
NetP11_4: P11.4 P12.4 | length 230.7
  Top Layer w8: P12.4@1340,1967.32 v1(1340,2025) P12.4@1340,2082.68
  Bottom Layer w8: P11.4@1340,1967.32 v1(1340,2025) P11.4@1340,2082.68
NetP11_5: P11.5 P12.5 | length 230.7
  Top Layer w8: P12.5@1240,1967.32 v1(1240,2025) P12.5@1240,2082.68
  Bottom Layer w8: P11.5@1240,1967.32 v1(1240,2025) P11.5@1240,2082.68
NetP11_6: P11.6 P12.6 | length 230.7
  Top Layer w8: P12.6@1140,1967.32 v1(1140,2025) P12.6@1140,2082.68
  Bottom Layer w8: P11.6@1140,1967.32 v1(1140,2025) P11.6@1140,2082.68
NetP11_8: P11.8 P12.8 | length 230.7
  Top Layer w8: P12.8@940,1967.32 P12.8@940,2082.68
  Bottom Layer w8: P11.8@940,1967.32 v1(940,2025) P11.8@940,2082.68
NetP11_9: P11.9 P12.9 | length 230.7
  Top Layer w8: P12.9@840,1967.32 v1(840,2025) P12.9@840,2082.68
  Bottom Layer w8: P11.9@840,1967.32 v1(840,2025) P11.9@840,2082.68
NetP11_10: P11.10 P12.10 | length 230.7
  Top Layer w8: P12.10@740,1967.32 v1(740,2025) P12.10@740,2082.68
  Bottom Layer w8: P11.10@740,1967.32 v1(740,2025) P11.10@740,2082.68
NetP14_1: P14.1 P15.1 | length 104.8
  Top Layer w12: v2(2467.5,1177.5) P15.1@2467.5,1225
  Bottom Layer w12: P14.1@2443.78,1225 2467.5,1201.28 v2(2467.5,1177.5)
NetP14_3: P14.3 P15.3 | length 104.8
  Top Layer w12: v2(2467.5,1077.5) P15.3@2467.5,1125
  Bottom Layer w12: P14.3@2443.78,1125 2467.5,1101.28 v2(2467.5,1077.5)
NetP14_4: P14.4 P15.4 | length 151.2
  Top Layer w12: P15.4@2642.5,1125 2729.84,1125 v1(2730,1124.84)
  Bottom Layer w12: P14.4@2666.38,1124.84 v1(2730,1124.84)
NetP14_5: P14.5 P15.5 | length 123.4
  Top Layer w12: P15.5@2467.5,1025 2498,1055.5 v2(2498,1065)
  Bottom Layer w12: P14.5@2443.78,1025 2458,1025 v2(2498,1065)
NetP14_6: P14.6 P15.6 | length 151.3
  Top Layer w12: P15.6@2642.5,1025 v1(2730,1025)
  Bottom Layer w12: P14.6@2666.22,1025 v1(2730,1025)
NetP17_1: P17.1 P18.1 | length 253.6
  Top Layer w15: P18.1@3500,1967.32 v1(3500,2025) P18.1@3500,2082.68
  Bottom Layer w6: P17.1@3500,1944.4 P17.1@3500,1967.32
  Bottom Layer w15: P17.1@3500,1967.32 v1(3500,2025) P17.1@3500,2082.68
NetP17_2: P17.2 P18.2 | length 253.6
  Top Layer w15: P18.2@3400,1967.32 v1(3400,2025) P18.2@3400,2082.68
  Bottom Layer w6: P17.2@3400,1944.4 P17.2@3400,1967.32
  Bottom Layer w15: P17.2@3400,1967.32 v1(3400,2025) P17.2@3400,2082.68
NetP17_3: P17.3 P18.3 | length 254.6
  Top Layer w15: P18.3@3300,1967.32 v1(3300,2025) P18.3@3300,2082.68
  Bottom Layer w6: P17.3@3300,1943.4 P17.3@3300,1967.32
  Bottom Layer w15: P17.3@3300,1967.32 v1(3300,2025) P17.3@3300,2082.68
NetP17_4: P17.4 P18.4 | length 245
  Top Layer w6: P18.4@3200,1943.4 P18.4@3200,1967.32
  Top Layer w15: P18.4@3200,1977 v1(3200,2025) P18.4@3200,2082.68
  Bottom Layer w15: P17.4@3200,1967.32 v1(3200,2025) P17.4@3200,2082.68
NetP17_5: P17.5 P18.5 | length 254.6
  Top Layer w6: P18.5@3100,1943.4 P18.5@3100,1967.32
  Top Layer w15: P18.5@3100,1967.32 v1(3100,2025) P18.5@3100,2082.68
  Bottom Layer w15: P17.5@3100,1967.32 v1(3100,2025) P17.5@3100,2082.68
NetP17_6: P17.6 P18.6 | length 246
  Top Layer w6: P18.6@3000,1944.4 P18.6@3000,1967.32
  Top Layer w15: P18.6@3000,1975 v1(3000,2025) P18.6@3000,2082.68
  Bottom Layer w15: P17.6@3000,1967.32 v1(3000,2025) P17.6@3000,2082.68
NetP17_7: P17.7 P18.7 | length 243
  Top Layer w6: P18.7@2900,1943.4 P18.7@2900,1967.32
  Top Layer w15: P18.7@2900,1979 v1(2900,2025) P18.7@2900,2082.68
  Bottom Layer w15: P17.7@2900,1967.32 v1(2900,2025) P17.7@2900,2082.68
NetP17_8: P17.8 P18.8 | length 253.6
  Top Layer w15: P18.8@2800,1967.32 v1(2800,2025) P18.8@2800,2082.68
  Bottom Layer w6: P17.8@2800,1944.4 P17.8@2800,1967.32
  Bottom Layer w15: P17.8@2800,1967.32 v1(2800,2025) P17.8@2800,2082.68
NetP17_9: P17.9 P18.9 | length 276.6
  Top Layer w15: P18.9@2700,1967.32 v1(2700,2025) P18.9@2700,2082.68
  Bottom Layer w6: P17.9@2700,1944.4 P17.9@2700,1967.32 P17.9@2700,1944.4
  Bottom Layer w15: P17.9@2700,1967.32 v1(2700,2025) P17.9@2700,2082.68
NetP22_2: P22.2 SW4.4 | length 600.4
  Top Layer w15: SW4.4@145.9,821.89 v1(188,821.89) ; v1(385,475) P22.2@465,475
  Bottom Layer w15: v1(188,821.89) 273.11,821.89 385,710 v1(385,475)
NetQ1_1: Q1.1 Q1.2 Q1.3 Q2.4 | length 230.9
  Top Layer w10: Q2.4@1873.01,1540.18 1888.82,1540.18 1905,1524 1905,1481 1915.88,1470.12 2034.3,1470.12 Q1.3@2045.18,1481
NetQ2_3: Q2.3 SB2.2 | length 49.3
  Top Layer w10: SB2.2@1900,1572.4 1903.78,1572.4 Q2.3@1936,1540.18
NetQ3_1: Q3.1 U1.17 | length 652.8
  Top Layer w6: U1.17@2279.53,1514.76 2279.53,1439.47 2358.81,1360.19 2358.81,980.52 2396.59,942.74 Q3.1@2396.59,910.46
NetQ4_3: Q4.3 U1.16 | length 851.5
  Top Layer w6: Q4.3@2215.54,805 2305.89,805 2316.96,816.07 2316.96,950.06 2346.91,980 2346.91,1355.26 2263.78,1438.38 U1.16@2263.78,1514.76
NetR3_1: R3.1 U3.2 | length 105.6
  Top Layer w15: U3.2@983,1666.73 983,1645.24 993,1635.24 v1(993,1629.5) ; v1@993,1565.24 v1(993,1575)
  Bottom Layer w15: v1(993,1575) v1(993,1629.5)
NetR4_1: R4.1 U4.2 | length 156
  Top Layer w15: R4.1@1137.75,1551.69 1163.03,1551.69 v1(1186.35,1575) ; v1@1203,1630.92 U4.2@1203,1666.73
  Bottom Layer w15: v1(1186.35,1575) 1186.35,1614.27 v1(1202.37,1630.29)
NetR11_2: R11.2 U6.7 | length 58.1
  Top Layer w6: R11.2@670,129.69 670.52,130.2 U6.7@727.86,130.2
NetR27_2: R27.2 R31.1 U7.6 | length 252.5
  Top Layer w8: R27.2@1136.77,1117.75 1136.77,999.99 1153.05,983.71 U7.6@1199.68,983.71 1201.09,985.13 1234.95,985.13 1241.69,978.39 R31.1@1261.35,978.39
NetR28_1: R28.1 R29.2 U7.5 | length 110.4
  Top Layer w8: R28.1@1136.77,909.25 R29.2@1179.87,909.26 U7.5@1179.87,955.72
  Top Layer w10: U7.5@1179.87,955.72 1182.27,958.12 U7.5@1199.68,958.12
NetR32_2: R32.2 U5.10 U10.4 | length 871.6
  Top Layer w10: U10.4@874.81,1316.96 R32.2@935.41,1316.96 ; U5.10@879.79,638.37 883,641.58 v2(883,664) ; v2(905,1200) 935.45,1230.45 R32.2@935.45,1317 935.45,1333.27 974.82,1372.64 974.82,1391.81
  Bottom Layer w10: v2(883,664) 883,721 861,743 861,829 887,855 887,1140 905,1158 v2(905,1200)
NetR33_1: R33.1 U5.6 | length 48.9
  Top Layer w10: U5.6@879.79,559.63 923.94,559.63 R33.1@927.31,563
NetR34_1: R34.1 U9.1 U9.2 | length 240.9
  Top Layer w8: U9.2@1034.32,597.8 1093.52,597.8 ; U9.1@1034.32,623.39 1083.18,623.39 1096.31,610.25 R34.1@1096.31,496
NetR34_2: R34.2 R38.1 U9.6 | length 193.7
  Top Layer w8: R34.2@1135.69,496 1135.69,556.06 1151.83,572.2 U9.6@1199.68,572.2 1257.11,572.2 R38.1@1261,568.32
NetR35_1: R35.1 R37.2 U9.5 | length 94.7
  Top Layer w12: U9.5@1199.68,546.61 1208.08,546.61 1208.08,497.61 R35.1@1209.69,496 R37.2@1244.73,496
NetR36_2: R36.2 U5.7 U9.3 | length 184.5
  Top Layer w10: U5.7@879.79,579.32 899.87,579.32 905.28,584.73 929,584.73 ; R36.2@928.31,607 928.31,585.42 929,584.73 ; U9.3@1034.32,572.2 1004.8,572.2 992.27,584.73 929,584.73
NetR39_1: R39.1 U11.7 U16.5 | length 479.3
  Top Layer w6: R39.1@1579.77,1270.43 1620.24,1229.97 1620.24,1068.29 1619.19,1067.24 1619.19,1038.06 1620.25,1037 1620.25,1008.45 1638.88,989.81 1680.71,989.81 1691.15,1000.24 1733.89,1000.24 1737.34,1003.69 U16.5@1737.34,1013.09
  Top Layer w8: U11.7@1518.33,1268.67 R39.1@1578.01,1268.67
NetR40_1: R40.1 U17.4 | length 34.4
  Top Layer w10: U17.4@1760.74,1135.82 R40.1@1795.13,1135.82
NetR42_1: R42.1 U12.7 U16.6 | length 337.6
  Top Layer w6: U12.7@1518.33,1052.14 1581.06,1052.14 1608.34,1024.85 1608.34,1003.51 1633.95,977.91 1685.65,977.91 1696.08,988.34 1741.92,988.34 1759.04,1005.46 1759.04,1025.4 1757.57,1026.87 U16.6@1737.34,1026.87
NetR43_1: R43.1 U13.7 U24.1 | length 344.4
  Top Layer w6: R43.1@1579.77,837.16 1579.77,833.72 1601.37,812.12 1601.54,812.12 1621.75,791.91 1621.75,676.25 1658,640 1670,640 1689.33,620.67 U24.1@1704.81,620.67
  Top Layer w8: U13.7@1518.33,835.6 R43.1@1578.21,835.6
NetR44_1: R44.1 U22.4 | length 32
  Top Layer w10: U22.4@1762.49,699.31 R44.1@1794.54,699.31
NetR46_1: R46.1 U14.7 U24.2 | length 190.5
  Top Layer w6: R46.1@1580.07,620.87 1671.13,620.87 1685.11,606.89 U24.2@1704.81,606.89
  Top Layer w8: U14.7@1518.33,619.07 R46.1@1578.27,619.07
NetR47_1: R47.1 R48.2 U25.5 | length 174.8
  Top Layer w10: U25.5@918.12,806.52 931.02,806.52 936.1,801.43 v1(949,801.43) 964.68,801.43 R48.2@969.76,806.52 ; v1(1012.13,746.16) R47.1@1012.13,769.33
  Bottom Layer w10: v1(949,801.43) 973.54,801.43 1012.13,762.83 v1(1012.13,746.16)
NetR48_1: R48.1 U5.18 | length 807.9
  Top Layer w10: v2(718,532) 694,556 694,589 704,599 U5.18@728.21,599 ; v2(720,436) 746.19,462.19 807.54,462.19 825.35,480 922,480 v2(942,500) ; v2(1012,711.49) 1037.51,737 1037.51,784.49 1018.48,803.52 R48.1@1012.13,803.52
  Bottom Layer w10: v2(718,532) 720,530 v2(720,436) ; v2(942,500) 942,560 1012,630 v2(1012,711.49)
NetSB1_2: SB1.2 U1.41 | length 2857.6
  Top Layer w6: SB1.2@437.6,1123 518.09,1203.49 518.09,1663.93 559.09,1704.93 559.09,1879.07 531.16,1907 v2(505,1907) ; v2(1467,1856) 1516.6,1856 1559.69,1899.09 2253.48,1899.09 2326.77,1825.8 U1.41@2326.77,1752.95
  Bottom Layer w6: v2(505,1907) 534.28,1877.72 698.02,1877.72 734.74,1841 871.16,1841 897.16,1867 1456,1867 v2(1467,1856)
NetSB5_2: SB5.2 U11.5 | length 54.5
  Top Layer w8: U11.5@1518.33,1217.49 1566.3,1217.49 SB5.2@1572.8,1217.49
NetSB6_2: SB6.2 U13.5 | length 54.5
  Top Layer w8: U13.5@1518.33,784.42 1565.99,784.42 SB6.2@1572.86,784.42
NetU15_4: U15.4 U16.1 | length 306.8
  Top Layer w6: v1@1680,1062.97 1688.54,1054.43 U16.1@1704.66,1054.43 ; v1(1733.45,1263.82) U15.4@1760.52,1263.82
  Bottom Layer w6: v1@1680,1062.97 1715.24,1062.97 1743,1090.73 1743,1254.26 v1(1733.45,1263.82)
  other v1: 1680,1064.97
NetU19_1: U19.1 U20.4 | length 460.8
  Top Layer w6: v1(1819.09,811.57) 1900.94,811.57 1920.05,830.68 U20.4@1953.36,830.68 ; v1@1869,1071.16 1871,1071.16 1885.66,1056.5 U19.1@1894.76,1056.5
  Bottom Layer w6: v1(1819.09,811.57) 1818.28,812.39 1818.28,823.99 1818.72,824.42 1818.72,841.58 1818.28,842.01 1818.28,985.79 1837.19,1004.7 1837.19,1052.95 1854.24,1070 v1(1867,1070)
OUT_ENABLE: R1.1 U1.12 U2.4 | length 1933.1
  Top Layer w6: v1(1686.57,1545.72) 1686.57,1514.65 1749.78,1451.43 1804.91,1451.43 1847.75,1408.59 2072.59,1408.59 2164.62,1500.62 2164.62,1537.99 2173.87,1547.24 U1.12@2184.06,1547.24
  Top Layer w8: U2.4@804.4,1761.22 804.4,1746.19 v1(832,1746.19) 851.89,1746.19 R1.1@858,1740.08
  Bottom Layer w6: v1(832,1746.19) 832,1785 902.09,1855.09 1424.91,1855.09 1448.61,1831.39 1475.56,1831.39 1500.45,1856.28 1613.21,1856.28 1676.47,1793.02 1676.47,1555.82 v1(1686.57,1545.72)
